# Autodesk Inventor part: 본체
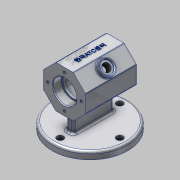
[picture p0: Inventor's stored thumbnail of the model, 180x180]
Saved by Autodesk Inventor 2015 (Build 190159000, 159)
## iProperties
Created: 2021-02
Part Number: 본체
Material: 알루미늄 6061
Document SubType Name: Modeling
Designer: Administrator
Density: 2.7 g/cm^3
Appearance: 알루미늄 - 평지
Author: Administrator
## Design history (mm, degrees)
sketch "스케치1"
  geometry: L1 (29, 12.012)-(29, -12.012); L2 (29, -12.012)-(12.012, -29); L3 (12.012, -29)-(-12.012, -29); L4 (-12.012, -29)-(-29, -12.012); L5 (-29, -12.012)-(-29, 12.012); L6 (-29, 12.012)-(-12.012, 29); L7 (-12.012, 29)-(12.012, 29); L8 (12.012, 29)-(29, 12.012)
  constraints: 16 end point
  dimensions: "d0" = 58 distance between parallel lines of L5 L1
extrude "돌출1" new body sketch "스케치1" distance "d3" = 70; taper "d4" = 0 deg
node "작업 평면1"
sketch "스케치2"
  geometry: L1 (0, 0)-(-12, 0); L2 (-12, 0)-(-12, -16); L3 (-12, -16)-(0, -16); L4 (0, -16)-(0, 0); L5 (-12, 0)-(-15, 0); L6 (-15, 0)-(-15, -14); L7 (-15, -14)-(-12, -14); L8 (-12, -14)-(-12, 0); L9 (-15, 0)-(-55, 0); L10 (-55, 0)-(-55, -22); L11 (-55, -22)-(-15, -22); L12 (-15, -22)-(-15, 0); L13 (-55, 0)-(-58, 0); L14 (-58, 0)-(-58, -14); L15 (-58, -14)-(-55, -14); L16 (-55, -14)-(-55, 0); L17 (-58, 0)-(-70, 0); L18 (-70, 0)-(-70, -16); L19 (-70, -16)-(-58, -16); L20 (-58, -16)-(-58, 0)
  constraints: 40 end point, 10 parallel, 5 horizontal, 5 perpendicular
  dimensions: "d6" = 12 distance of L3.end L2.end; "d7" = 16 distance of L2.end L1.end; "d8" = 3 distance of L7.end L6.end; "d9" = 14 distance of L6.end L5.end; "d10" = 40 distance of L11.end L10.end; "d11" = 22 distance of L10.end L9.end; "d12" = 3 distance of L15.end L14.end; "d13" = 14 distance of L14.end L13.end; "d14" = 12 distance of L19.end L18.end; "d15" = 16 distance of L18.end L17.end
revolve "회전1" sketch "스케치2" stored, may be unused: angle "d16" = 90 deg
sketch "스케치3"
  geometry: 1 further point
chamfer "모따기1" distance "d17" = 1; stored, may be unused: second distance "d18" = 2, angle "d19" = 45 deg
fillet "모깎기1" dims "d20" = 0.3
fillet "모깎기2" dims "d21" = 3
node "작업 평면2"
sketch "스케치4"
  geometry: L1 (0, 0)-(0, 24.024) reference; L2 (0, 41.012)-(70, 41.012) reference; C1 r 10 at (35, 12.012); 1 further point
  constraints: 1 centre point
  dimensions: "d23" = 10 radius of C1; "d24" = 35 distance from line of C1.centre L1; "d25" = 29 distance from line of L2 C1.centre
extrude "돌출2" join sketch "스케치4" distance "d26" = 5; taper "d27" = 0 deg
sketch "스케치5"
  geometry: L1 (0, 0)-(0, 24.024) reference; L2 (0, 41.012)-(70, 41.012) reference; C1 r 8 at (35, 12.012); 1 further point
  constraints: 1 centre point
  dimensions: "d28" = 8 radius of C1; "d29" = 35 distance from line of L1 C1.centre; "d30" = 29 distance from line of L2 C1.centre
extrude "돌출3" cut sketch "스케치5" distance "d31" = 2; taper "d32" = 0 deg
sketch "스케치6"
  geometry: C1 r 8 at (0, 0) reference; 2 further points
  constraints: 1 coincident
hole "구멍1" sketch "스케치6" at (0, 0) diameter "d33" = 10.917; stored, may be unused: countersink angle "d37" = 90 deg, drill point angle "d39" = 0 deg; dims "d34" = 24, "d35" = 4, "d36" = 2, "d38" = 29.1
fillet "모깎기3" dims "d40" = 1
chamfer "모따기2" distance "d41" = 1; stored, may be unused: second distance "d42" = 2, angle "d43" = 45 deg
node "작업 평면3"
sketch "스케치7"
  geometry: C1 r 52 at (-35, 0); 1 further point
  constraints: 1 centre point
  dimensions: "d50" = 52 radius of C1
extrude "돌출4" join sketch "스케치7" distance "d51" = 10; taper "d52" = 0 deg
sketch "스케치8"
  geometry: L1 (-28, -5)-(28, -5); L2 (28, -5)-(28, 5); L3 (28, 5)-(-28, 5); L4 (-28, 5)-(-28, -5); C1 r 52 at (0, 0) reference; 1 further point
  constraints: 8 end point, 2 parallel, 1 horizontal, 1 perpendicular
  dimensions: "d53" = 56 distance of L3.end L2.end; "d54" = 10 distance of L2.end L1.end; "d55" = 5 distance from line of L1 C1.centre; "d56" = 28 distance from line of L4 C1.centre
extrude "돌출5" join sketch "스케치8" stored distance "d57" = 10; taper "d58" = 0 deg
sketch "스케치9"
  geometry: C1 r 52 at (0, 0) reference; C2 r 4.5 at (0, 41); C3 r 4.5 at (41, 0); C4 r 4.5 at (0, -41); C5 r 4.5 at (-41, 0); A1 r 41 centre (0, 0) between (0, 41) and (41, 0); 1 further point
  constraints: 5 centre point, 4 point on circle, 1 coincident
  dimensions: "d59" = 41 radius of A1; "d60" = 4.5 radius of C2; "d61" = 4.5 radius of C3; "d62" = 4.5 radius of C4; "d63" = 4.5 radius of C5
extrude "돌출6" cut sketch "스케치9" stored distance "d64" = 10; taper "d65" = 0 deg
sketch "스케치10"
  geometry: C1 r 17 at (0, 0) reference; A1 r 23 centre (0, 0) between (0, 23) and (23, 0); 2 further points
  constraints: 4 point on circle, 1 centre point, 1 coincident
  dimensions: "d66" = 23 radius of A1
hole "구멍2" sketch "스케치10" at (0, 23), (23, 0), (0, -23), (-23, 0) diameter "d67" = 3.242; stored, may be unused: countersink angle "d71" = 90 deg, drill point angle "d73" = 118 deg; dims "d68" = 8, "d69" = 4, "d70" = 2, "d72" = 10
sketch "스케치11"
  geometry: C1 r 17 at (0, 0) reference; A1 r 23 centre (0, 0) between (0, 23) and (23, 0); 2 further points
  constraints: 4 point on circle, 1 centre point, 1 coincident
  dimensions: "d74" = 23 radius of A1
hole "구멍3" sketch "스케치11" at (0, 23), (23, 0), (0, -23), (-23, 0) diameter "d75" = 3.242; stored, may be unused: countersink angle "d79" = 90 deg, drill point angle "d81" = 118 deg; dims "d76" = 8, "d77" = 4, "d78" = 2, "d80" = 10
fillet "모깎기4" dims "d82" = 3
fillet "모깎기5" dims "d83" = 3
fillet "모깎기6" dims "d84" = 3
fillet "모깎기7" dims "d85" = 1
sketch "스케치12"
  geometry: L1 (0, 0)-(0, 23.196) reference; L2 (0, 40.305)-(70, 40.305) reference; 2 further points
  constraints: 1 other
  dimensions: "d86" = 35 distance from line of L1 point (35, 11.305); "d87" = 29 distance from line of L2 point (35, 11.305)
feature "엠보싱1" sketch "스케치12" dims "d0" = 58, "d6" = 12, "d7" = 16, "d8" = 3, "d9" = 14, "d10" = 40, "d11" = 22, "d12" = 3, "d13" = 14, "d14" = 12, "d15" = 16, "d88" = 0.5, "d89" = 0
node "솔리드1"
other parameters: "d5" = 0, "d22" = 5, "d44" = -62
